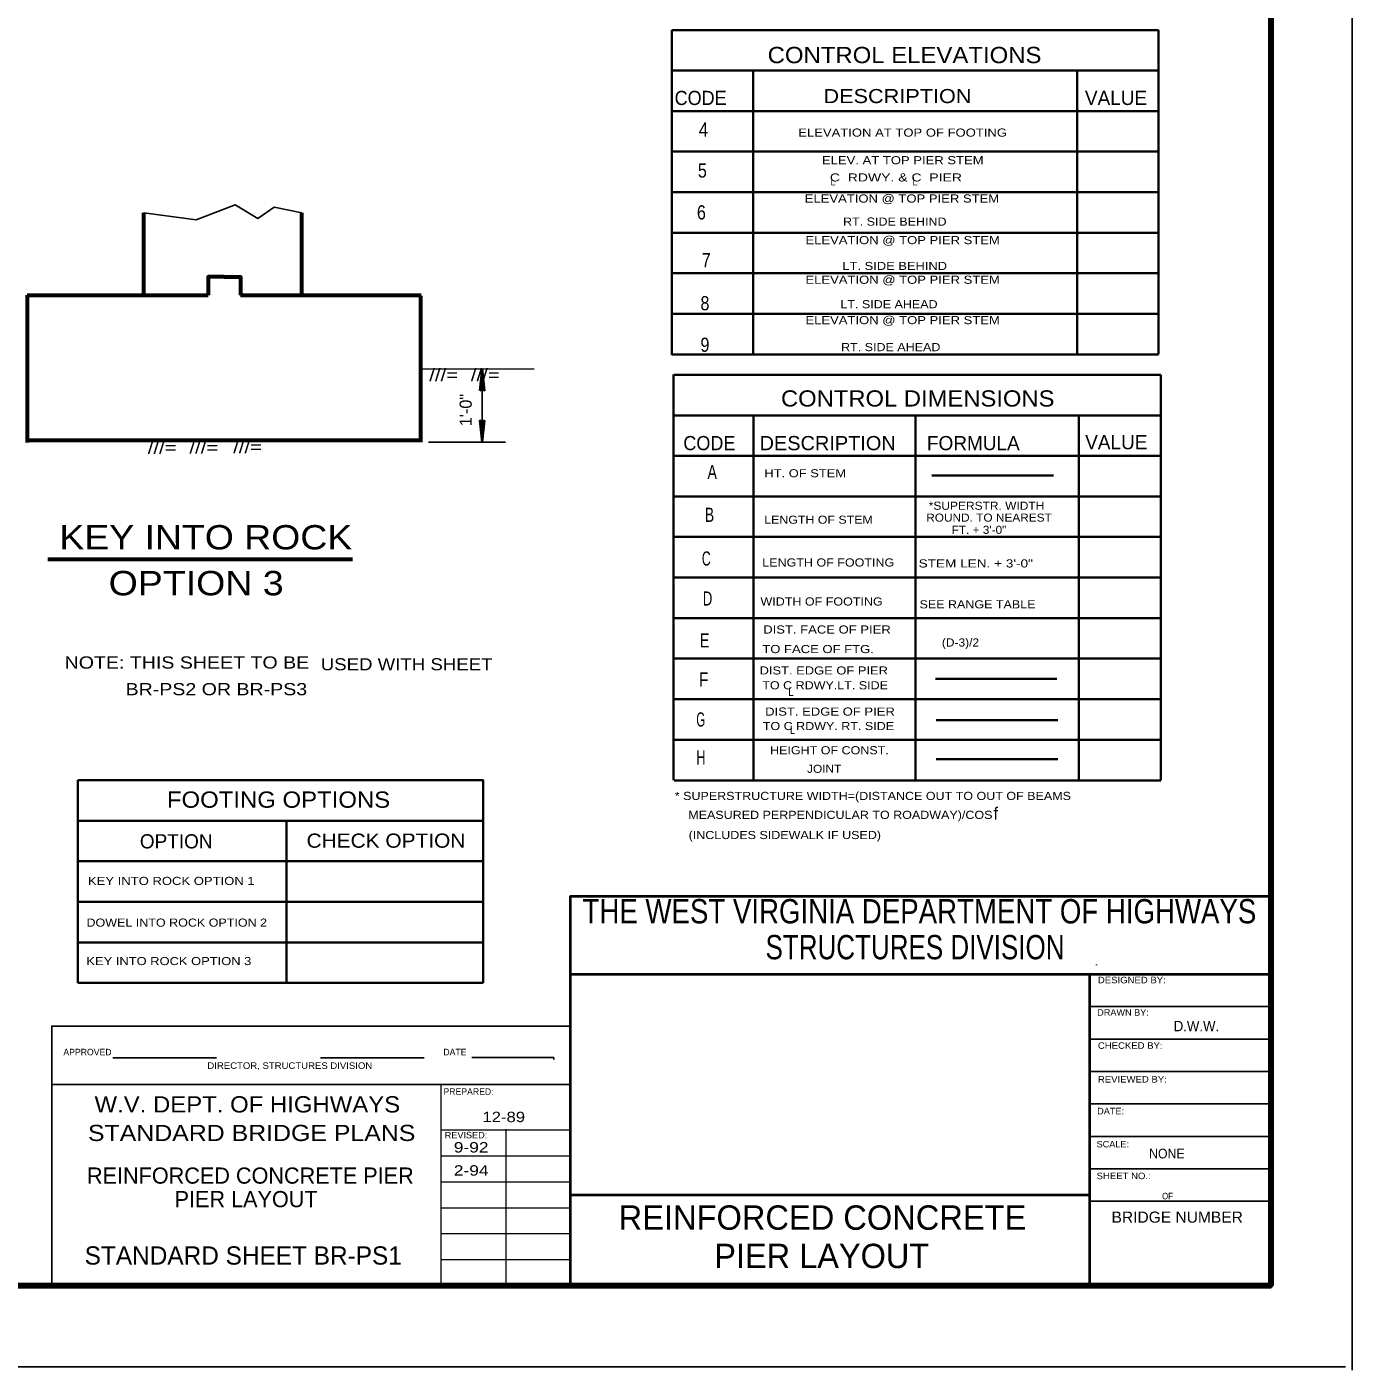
# Model space of a CAD drawing. Extents: x 1.6 to 19.9, y 2.8 to 9.5.
# Drawn here: x 18.624 to 19.901, y 7.285 to 8.58 of the extents above; entities that cross this region are included whole.
import ezdxf
from ezdxf.enums import TextEntityAlignment as Align

# ---------------------------------------------------------------- set-up
doc = ezdxf.new("R2010")
doc.units = 0
doc.header["$LTSCALE"] = 0.0047
doc.header["$PDMODE"] = 32
doc.header["$PDSIZE"] = 0.00235
doc.linetypes.add('DOTTED', pattern=[1.5, 0.3, -1.2])
doc.layers.add('1', color=7, linetype='Continuous', lineweight=35)
doc.layers.add('5', color=7, linetype='Continuous', lineweight=13)

msp = doc.modelspace()

# ---------------------------------------------------------------- linework, layer by layer
at = {"layer": '1', "lineweight": 25}
for p, q in [((19.901167, 7.2855), (19.901167, 9.543917)), ((18.736833, 8.3225), (18.736833, 8.322)), ((18.889167, 8.3225), (18.889167, 8.322)), ((19.062667, 8.179667), (19.062667, 8.250083)), ((19.654917, 7.67575), (19.654917, 7.676333)), ((19.648, 7.63575), (19.823, 7.63575)), ((19.648, 7.6045), (19.823, 7.6045)), ((19.648, 7.57325), (19.823, 7.57325)), ((18.648, 7.56075), (19.148, 7.56075)), ((19.648, 7.542), (19.823, 7.542)), ((19.648, 7.51075), (19.823, 7.51075)), ((19.648, 7.4795), (19.823, 7.4795)), ((19.648, 7.44825), (19.823, 7.44825)), ((16.26675, 7.288833), (19.894917, 7.288833))]:
    msp.add_line(p, q, dxfattribs=at)
at = {"layer": '1'}
for p, q in [((19.245667, 8.576667), (19.714417, 8.576667)), ((19.245667, 8.26375), (19.245667, 8.576667)), ((19.714417, 8.576667), (19.714417, 8.26425)), ((19.245667, 8.537583), (19.714417, 8.537583)), ((19.323833, 8.26375), (19.323833, 8.537583)), ((19.636333, 8.26375), (19.636333, 8.537583)), ((19.245667, 8.4985), (19.714417, 8.4985)), ((19.245667, 8.4595), (19.714417, 8.4595)), ((19.245667, 8.420417), (19.714417, 8.420417)), ((19.714417, 8.381333), (19.245667, 8.381333)), ((19.714417, 8.34225), (19.245667, 8.34225)), ((19.714417, 8.30325), (19.245667, 8.30325)), ((19.714417, 8.264167), (19.245667, 8.264167)), ((19.06075, 8.229833), (19.062417, 8.24525)), ((19.06075, 8.22975), (19.062417, 8.24525)), ((19.060833, 8.22975), (19.062583, 8.24525)), ((19.061, 8.22975), (19.062667, 8.245167)), ((19.061167, 8.22975), (19.062917, 8.245167)), ((19.062667, 8.229417), (19.062667, 8.250083)), ((19.06425, 8.22975), (19.062667, 8.244167)), ((19.0645, 8.22975), (19.062917, 8.24425)), ((19.06475, 8.229833), (19.063083, 8.24425)), ((19.247083, 7.854), (19.247083, 8.244667)), ((19.247917, 8.2445), (19.716667, 8.2445)), ((19.716667, 8.2445), (19.716667, 7.854)), ((19.064, 8.22975), (19.062417, 8.244083)), ((19.247917, 8.205417), (19.716667, 8.205417)), ((19.32425, 7.853083), (19.32425, 8.205333)), ((19.4805, 7.854), (19.4805, 8.20575)), ((19.63775, 7.854), (19.63775, 8.205333)), ((19.06075, 8.2), (19.062417, 8.1855)), ((19.061, 8.2), (19.062583, 8.1855)), ((19.061167, 8.2), (19.06275, 8.185583)), ((19.061417, 8.2), (19.063083, 8.185667)), ((19.062667, 8.200333), (19.062667, 8.179667)), ((19.064333, 8.2), (19.062667, 8.1845)), ((19.0645, 8.2), (19.06275, 8.1845)), ((19.064667, 8.2), (19.063, 8.1845)), ((19.064833, 8.2), (19.063083, 8.1845)), ((19.06475, 8.2), (19.063083, 8.1845)), ((19.063083, 8.198917), (19.063083, 8.18975)), ((19.247917, 8.166333), (19.716667, 8.166333)), ((19.247917, 8.12725), (19.716667, 8.12725)), ((19.247917, 8.08825), (19.716667, 8.08825)), ((19.716667, 8.049083), (19.247917, 8.049083)), ((19.716667, 8.01), (19.247917, 8.01)), ((19.716667, 7.971), (19.247917, 7.971)), ((19.716667, 7.931917), (19.247917, 7.931917)), ((19.716667, 7.892833), (19.247917, 7.892833)), ((18.67325, 7.6585), (18.67325, 7.853833)), ((19.716667, 7.85375), (19.247917, 7.85375)), ((18.67325, 7.81475), (19.063917, 7.81475)), ((18.874167, 7.6585), (18.874167, 7.8145)), ((18.67325, 7.77575), (19.063917, 7.77575)), ((18.67325, 7.736667), (19.063917, 7.736667)), ((19.063917, 7.697583), (18.67325, 7.697583)), ((19.063917, 7.6585), (18.67325, 7.6585))]:
    msp.add_line(p, q, dxfattribs=at)
at = {"layer": '1', "lineweight": 60}
for p, q in [((18.62425, 8.32125), (18.798667, 8.32125)), ((18.829917, 8.32125), (19.003917, 8.32125)), ((19.003333, 8.320583), (19.003333, 8.1795)), ((18.623167, 8.181417), (19.00225, 8.181583)), ((18.644167, 8.06675), (18.938, 8.06675))]:
    msp.add_line(p, q, dxfattribs=at)
at = {"layer": '1', "lineweight": 13}
for p, q in [((19.246083, 8.2445), (19.714833, 8.2445)), ((19.023, 7.56075), (19.023, 7.367)), ((19.023, 7.517), (19.148, 7.517)), ((19.0855, 7.517583), (19.0855, 7.367)), ((19.023, 7.492), (19.148, 7.492)), ((19.023, 7.467), (19.148, 7.467)), ((19.023, 7.442), (19.148, 7.442)), ((19.023, 7.417), (19.148, 7.417)), ((19.023, 7.392), (19.148, 7.392))]:
    msp.add_line(p, q, dxfattribs=at)
at = {"layer": '1', "lineweight": 40}
for p, q in [((19.148, 7.667), (19.823, 7.667)), ((19.648, 7.667), (19.648, 7.367)), ((19.148, 7.4545), (19.648, 7.4545))]:
    msp.add_line(p, q, dxfattribs=at)
at = {"layer": '1', "linetype": 'DOTTED', "lineweight": 25}
msp.add_line((18.706917, 7.58625), (19.023417, 7.58625), dxfattribs=at)
at = {"layer": '1', "lineweight": 106}
msp.add_line((16.423, 7.367), (19.823, 7.367), dxfattribs=at)
msp.add_lwpolyline([(19.823, 7.367), (19.823, 9.467), (16.423, 9.467), (16.423, 7.367)], dxfattribs=at)
at = {"layer": '1', "lineweight": 60}
for points in [[(18.814333, 8.339), (18.798667, 8.339), (18.798667, 8.321083)], [(18.814333, 8.339), (18.829917, 8.339), (18.829917, 8.321083)], [(18.62425, 8.321083), (18.62425, 8.2275), (18.62425, 8.179333)]]:
    msp.add_lwpolyline(points, dxfattribs=at)
at = {"layer": '1'}
for points in [[(19.060417, 8.229417), (19.062667, 8.250083), (19.065083, 8.229417), (19.062667, 8.2305)], [(19.065083, 8.200333), (19.062667, 8.179667), (19.060417, 8.200333), (19.06275, 8.19925)]]:
    msp.add_lwpolyline(points, close=True, dxfattribs=at)
for points in [[(19.062417, 8.23075), (19.062333, 8.24), (19.062667, 8.24), (19.062417, 8.23825), (19.062333, 8.23075), (19.062167, 8.23675), (19.062, 8.230583), (19.061917, 8.234833), (19.061667, 8.230333), (19.062167, 8.2375), (19.062667, 8.246667), (19.063083, 8.24475), (19.062917, 8.24725), (19.062917, 8.23075), (19.06325, 8.235667), (19.06325, 8.230583), (19.062583, 8.241083), (19.063667, 8.230417), (19.062583, 8.230917), (19.061083, 8.23), (19.061417, 8.230417), (19.062167, 8.230917), (19.062, 8.231333), (19.061333, 8.231), (19.06275, 8.23075), (19.063667, 8.230333), (19.064667, 8.229833)], [(19.062667, 8.1825), (19.062583, 8.198917), (19.06225, 8.194167), (19.06225, 8.19925), (19.063, 8.188583), (19.06175, 8.199333), (19.063, 8.198833), (19.064417, 8.19975), (19.064167, 8.199333), (19.063333, 8.198833), (19.0635, 8.198417), (19.064167, 8.19875), (19.062667, 8.199), (19.06175, 8.1995), (19.060833, 8.2)], [(19.062917, 8.18975), (19.063083, 8.1915), (19.063083, 8.198917), (19.063417, 8.193), (19.063417, 8.19925), (19.063583, 8.194833), (19.063833, 8.199417), (19.063333, 8.19225), (19.062917, 8.183083)], [(18.67325, 7.853833), (19.063917, 7.853833), (19.063917, 7.6585)]]:
    msp.add_lwpolyline(points, dxfattribs=at)
at = {"layer": '1', "lineweight": 40}
msp.add_lwpolyline([(16.423, 7.367), (19.148, 7.367), (19.148, 7.742), (19.823, 7.742)], dxfattribs=at)
at = {"layer": '1', "lineweight": 25}
msp.add_lwpolyline([(18.648, 7.367), (18.648, 7.617), (19.148, 7.617)], dxfattribs=at)
at = {"layer": '1', "linetype": 'DOTTED', "lineweight": 25}
msp.add_lwpolyline([(19.053, 7.58675), (19.13175, 7.58675), (19.13175, 7.584833)], dxfattribs=at)
at = {"layer": '1'}
msp.add_point((19.823, 7.367), dxfattribs=at)
at = {"layer": '5', "lineweight": 60}
for p, q in [((18.736833, 8.3225), (18.736833, 8.400583)), ((18.889167, 8.3225), (18.889167, 8.400583))]:
    msp.add_line(p, q, dxfattribs=at)
at = {"layer": '5'}
msp.add_line((19.003167, 8.25025), (19.113, 8.25025), dxfattribs=at)
at = {"layer": '5', "lineweight": 25}
msp.add_line((19.011167, 8.179667), (19.085167, 8.179667), dxfattribs=at)
at = {"layer": '5', "lineweight": 35}
for p, q in [((19.496167, 8.1475), (19.613417, 8.1475)), ((19.499583, 7.951583), (19.61675, 7.951583)), ((19.500167, 7.911583), (19.617417, 7.911583)), ((19.500167, 7.874167), (19.617417, 7.874167))]:
    msp.add_line(p, q, dxfattribs=at)
at = {"layer": '5', "lineweight": 25}
msp.add_lwpolyline([(18.736833, 8.400583), (18.787083, 8.393833), (18.824667, 8.40825), (18.846667, 8.395), (18.86225, 8.406), (18.889167, 8.400583)], dxfattribs=at)

# ---------------------------------------------------------------- texts
at = {"layer": '1'}
for s, height, width, p in [('CONTROL ELEVATIONS', 0.01567, 1.1, (19.337917, 8.54475)), ('CODE', 0.01367, 0.95, (19.24825, 8.504417)), ('DESCRIPTION ', 0.01358, 1.15, (19.391667, 8.50625)), ('4', 0.01367, 0.9, (19.2715, 8.473917)), ('ELEVATION AT TOP OF FOOTING', 0.007833, 1.2, (19.367417, 8.473917)), ('ELEV. AT TOP PIER STEM', 0.007833, 1.2, (19.39025, 8.447333)), ('5', 0.01367, 0.85, (19.270667, 8.4345)), ('6', 0.01367, 0.85, (19.26975, 8.394167)), ('CONTROL DIMENSIONS', 0.01558, 1.1, (19.35075, 8.213917)), ('CODE', 0.01367, 0.95, (19.256667, 8.171833)), ('DESCRIPTION', 0.01367, 1.05, (19.330167, 8.171833)), ('A', 0.01367, 0.75, (19.279917, 8.144)), ('HT. OF STEM ', 0.00775, 1.2, (19.33475, 8.14575)), ('B', 0.01367, 0.75, (19.27725, 8.10275)), ('*SUPERSTR. WIDTH', 0.007833, 1.1, (19.493167, 8.114417)), ('LENGTH OF STEM', 0.00775, 1.15, (19.334583, 8.101)), ('ROUND. TO NEAREST', 0.00775, 1.1, (19.49075, 8.103)), ('FT. + 3\'-0"', 0.00775, 1.1, (19.515167, 8.09125)), ('C', 0.01367, 0.65, (19.2745, 8.060667)), ('LENGTH OF FOOTING', 0.007833, 1.15, (19.33275, 8.05975)), ('STEM LEN. + 3\'-0"', 0.007833, 1.25, (19.483417, 8.058833)), ('D', 0.01358, 0.7, (19.275417, 8.022167)), ('WIDTH OF FOOTING', 0.007833, 1.15, (19.331, 8.022167)), ('SEE RANGE TABLE', 0.007833, 1.15, (19.48425, 8.019417)), ('DIST. FACE OF PIER', 0.007833, 1.2, (19.333667, 7.995167)), ('E', 0.01367, 0.75, (19.272667, 7.98175)), ('(D-3)/2', 0.007833, 1.1, (19.505833, 7.982667)), ('NOTE: THIS SHEET TO BE', 0.01175, 1.2, (18.660417, 7.961417)), ('TO FACE OF FTG.', 0.007833, 1.2, (19.33275, 7.976333)), ('USED WITH SHEET', 0.01167, 1.15, (18.90725, 7.95975)), ('DIST. EDGE OF PIER', 0.00775, 1.2, (19.330167, 7.95575)), ('BR-PS2 OR BR-PS3', 0.01175, 1.2, (18.719167, 7.93575)), ('F', 0.01367, 0.8, (19.271833, 7.944083)), ('TO C RDWY.LT. SIDE', 0.007833, 1.15, (19.33275, 7.941417)), ('L', 0.007833, 0.85, (19.357917, 7.935083)), ('DIST. EDGE OF PIER', 0.007833, 1.2, (19.3355, 7.916083)), ('G', 0.01367, 0.6, (19.269167, 7.905583)), ('TO C RDWY. RT. SIDE', 0.007833, 1.15, (19.33325, 7.902167)), ('L', 0.007833, 0.85, (19.359417, 7.8985)), ('H', 0.01367, 0.65, (19.269333, 7.869)), ('CHECK OPTION', 0.01367, 1.1, (18.893583, 7.788833)), ('KEY INTO ROCK OPTION 1', 0.007833, 1.2, (18.682917, 7.752917)), ('DOWEL INTO ROCK OPTION 2', 0.007833, 1.15, (18.6815, 7.71275)), ('KEY INTO ROCK OPTION 3', 0.00775, 1.2, (18.681417, 7.67575)), ('DESIGNED BY:', 0.006251, 1.1, (19.656167, 7.65825)), ('DRAWN BY:', 0.006251, 1.05, (19.6555, 7.627)), ('CHECKED BY:', 0.006251, 1.1, (19.656167, 7.595083)), ('DIRECTOR, STRUCTURES DIVISION', 0.006251, 1.1, (18.798, 7.57575)), ('REVIEWED BY:', 0.006251, 1.1, (19.656167, 7.562583)), ('W.V. DEPT. OF HIGHWAYS', 0.01567, 1.1, (18.68925, 7.53375)), ('DATE:', 0.006251, 1.05, (19.6555, 7.532)), ('STANDARD BRIDGE PLANS', 0.01558, 1.15, (18.682917, 7.50625)), ('REVISED:', 0.006251, 1.05, (19.02675, 7.508833)), ('SCALE:', 0.006251, 1.05, (19.654917, 7.500083)), ('NONE', 0.009333, 0.95, (19.7055, 7.4895)), ('SHEET NO.:', 0.006251, 1.1, (19.654917, 7.4695)), ('OF', 0.006251, 0.9, (19.718, 7.450083))]:
    msp.add_text(s, height=height, dxfattribs=dict(at, width=width)).set_placement(p)
for s, height, p in [('VALUE', 0.01367, (19.643667, 8.504417)), ('FORMULA', 0.01367, (19.491417, 8.171833)), ('VALUE', 0.01367, (19.643917, 8.17275)), ('f ', 0.01175, (19.555583, 7.816)), ('OPTION', 0.01367, (18.732917, 7.788167)), ('APPROVED', 0.00625, (18.65925, 7.588833)), ('DATE', 0.00625, (19.025417, 7.588833)), ('PREPARED:', 0.006251, (19.0255, 7.55075)), ('REINFORCED CONCRETE PIER', 0.01558, (18.682, 7.465167)), ('PIER LAYOUT', 0.01558, (18.766417, 7.4425)), ('REINFORCED CONCRETE', 0.0235, (19.194333, 7.42075)), ('STANDARD SHEET BR-PS1', 0.01758, (18.67975, 7.387167)), ('PIER LAYOUT', 0.02342, (19.2865, 7.383833))]:
    msp.add_text(s, height=height, dxfattribs=at).set_placement(p)
for s, height, width, p in [('OPTION 3', 0.0235, 1.15, (18.787167, 8.032)), ('HEIGHT OF CONST.', 0.007833, 1.15, (19.397458, 7.878833)), ('JOINT', 0.00775, 1.1, (19.392417, 7.861)), ('FOOTING OPTIONS', 0.01567, 1.1, (18.866583, 7.827333)), ('THE WEST VIRGINIA DEPARTMENT OF HIGHWAYS', 0.02342, 0.85, (19.484167, 7.715917)), ('STRUCTURES DIVISION', 0.02342, 0.8, (19.479917, 7.681333)), ('D.W.W.', 0.01, 0.95, (19.751125, 7.612)), ('12-89', 0.01, 1.2, (19.083583, 7.524417)), ('9-92', 0.01, 1.25, (19.052208, 7.495167)), ('2-94', 0.01, 1.25, (19.052208, 7.472917)), ('BRIDGE NUMBER', 0.01067, 1.05, (19.732583, 7.427583))]:
    msp.add_text(s, height=height, dxfattribs=dict(at, width=width)).set_placement(p, align=Align.CENTER)
at = {"layer": '5'}
for s, height, width, p in [('C  RDWY. & C  PIER', 0.00775, 1.3, (19.397917, 8.43075)), ('L', 0.007833, 0.85, (19.3985, 8.426917)), ('L', 0.007833, 0.85, (19.477417, 8.426917)), ('ELEVATION @ TOP PIER STEM', 0.007833, 1.2, (19.373667, 8.410417)), ('RT. SIDE BEHIND', 0.007833, 1.15, (19.410583, 8.388167)), ('ELEVATION @ TOP PIER STEM', 0.007833, 1.2, (19.374333, 8.370333)), ('7', 0.01367, 0.85, (19.274417, 8.348083)), ('LT. SIDE BEHIND', 0.00775, 1.2, (19.409917, 8.3455)), ('ELEVATION @ TOP PIER STEM', 0.007833, 1.2, (19.374333, 8.332167)), ('8', 0.01367, 0.85, (19.273167, 8.306667)), ('LT. SIDE AHEAD', 0.007833, 1.15, (19.408, 8.308583)), ('ELEVATION @ TOP PIER STEM', 0.007833, 1.2, (19.374333, 8.29325)), ('9', 0.01367, 0.85, (19.273167, 8.266583)), ('RT. SIDE AHEAD', 0.007833, 1.15, (19.408667, 8.26725)), ('KEY INTO ROCK', 0.02342, 1.15, (18.655417, 8.07625)), ('* SUPERSTRUCTURE WIDTH=(DISTANCE OUT TO OUT OF BEAMS', 0.007833, 1.15, (19.248417, 7.834833)), ('MEASURED PERPENDICULAR TO ROADWAY)/COS ', 0.007833, 1.15, (19.261417, 7.816583)), ('(INCLUDES SIDEWALK IF USED)', 0.007833, 1.15, (19.26175, 7.797167))]:
    msp.add_text(s, height=height, dxfattribs=dict(at, width=width)).set_placement(p)
at = {"layer": '5', "width": 1.25}
for height, p in [(0.01175, (19.02575, 8.2385)), (0.01175, (19.065833, 8.2385)), (0.01167, (18.754458, 8.1685)), (0.01175, (18.794583, 8.168583)), (0.01167, (18.836708, 8.169083))]:
    msp.add_text('///=', height=height, dxfattribs=at).set_placement(p, align=Align.CENTER)
at = {"layer": '5'}
msp.add_text('1\'-0"', height=0.01167, rotation=90, dxfattribs=at).set_placement((19.05275, 8.195))

doc.saveas('drawing.dxf')
